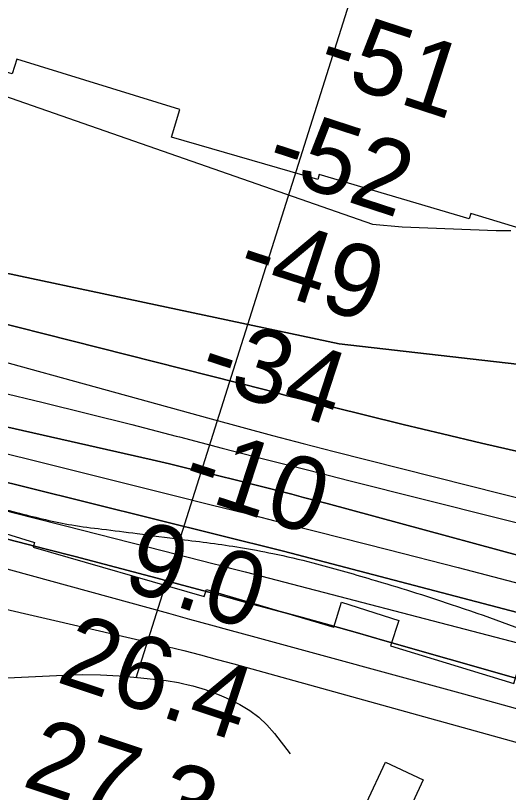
# Model space of a CAD drawing. Extents: x 3361039 to 3398939, y 576572 to 602007.
# Drawn here: x 3389803 to 3390253, y 585118 to 585828 of the extents above; entities that cross this region are included whole.
import ezdxf

# ---------------------------------------------------------------- set-up
doc = ezdxf.new("R2010")
doc.units = 0
for name, color, linetype in [('V-BLDG-OTLN', 7, 'Continuous'), ('V-CHAN-NAID', 7, 'Continuous'), ('V-RIVR-EDGE', 7, 'Continuous'), ('V-RIVR-RANG', 7, 'Continuous'), ('V-RRAP-RVMT', 7, 'Continuous'), ('V-TOPO-DPTH', 7, 'Continuous'), ('V-TOPO-MAJR', 7, 'Continuous'), ('V-TOPO-MINR', 7, 'Continuous'), ('V-TOPO-WATR', 7, 'Continuous'), ('V-UTIL-LINE', 7, 'Continuous')]:
    doc.layers.add(name, color=color, linetype=linetype)

msp = doc.modelspace()

# ---------------------------------------------------------------- linework, layer by layer
at = {"layer": 'V-BLDG-OTLN'}
msp.add_lwpolyline([(3390157.86, 585092.69), (3390123.44, 585108.75), (3390140.7, 585145.73), (3390175.12, 585129.67)], close=True, dxfattribs=at)
at = {"layer": 'V-RIVR-EDGE'}
msp.add_spline([(3387368.61, 585771.04), (3387388.99, 585767.6), (3387407.26, 585766.09), (3387418.22, 585761.68), (3387425.51, 585756.54), (3387441.59, 585752.85), (3387452.55, 585751.36), (3387462.06, 585753.9), (3387477.43, 585758.24), (3387482.91, 585759.33), (3387491.69, 585759.31), (3387502.28, 585758.18), (3387510.32, 585756.34), (3387521.64, 585753.02), (3387530.05, 585752.27), (3387538.46, 585752.24), (3387549.79, 585752.22), (3387558.94, 585755.48), (3387571.37, 585756.92), (3387583.43, 585757.25), (3387598.42, 585756.12), (3387629.84, 585749.46), (3387659.8, 585743.54), (3387703.28, 585736.85), (3387727.4, 585734.23), (3387739.1, 585733.47), (3387750.8, 585734.17), (3387753.72, 585731.61), (3387763.2, 585723.91), (3387774.52, 585720.59), (3387790.61, 585719.82), (3387800.12, 585721.62), (3387814, 585720.13), (3387824.6, 585720.1), (3387847.25, 585714.2), (3387884.16, 585709.35), (3387930.2, 585702.66), (3387980.65, 585701.07), (3388035.1, 585696.55), (3388076.04, 585694.62), (3388096.87, 585693.84), (3388120.26, 585690.49), (3388145.1, 585685.31), (3388171.78, 585682.32), (3388198.82, 585676.77), (3388222.56, 585669.4), (3388245.57, 585660.57), (3388260.91, 585655.42), (3388279.55, 585655.37), (3388291.26, 585658.26), (3388298.95, 585663.73), (3388299.32, 585666.29), (3388298.96, 585670.67), (3388290.56, 585674.35), (3388291.67, 585677.27), (3388293.86, 585678.36), (3388303, 585677.61), (3388318.72, 585676.47), (3388334.06, 585672.78), (3388354.14, 585663.59), (3388357.06, 585659.93), (3388363.27, 585658.09), (3388368.39, 585658.07), (3388370.95, 585660.99), (3388375.34, 585662.08), (3388379, 585661.34), (3388383.01, 585659.13), (3388383.73, 585654.38), (3388384.08, 585649.26), (3388389.93, 585647.42), (3388406, 585642.26), (3388468.86, 585637.72), (3388491.52, 585635.84), (3388534.64, 585628.42), (3388578.12, 585619.17), (3388610.64, 585613.61), (3388635.85, 585612.08), (3388727.94, 585599.43), (3388768.5, 585591.65), (3388822.57, 585580.92), (3388864.95, 585570.58), (3388906.6, 585562.8), (3388924.14, 585559.46), (3388938.77, 585561.99), (3388961.44, 585563.39), (3388974.22, 585560.07), (3389007.47, 585553.41), (3389018.81, 585554.48), (3389027.22, 585555.92), (3389037.09, 585555.89), (3389051.7, 585553.67), (3389061.21, 585553.28), (3389081.31, 585552.13), (3389098.12, 585550.99), (3389120.42, 585548.74), (3389143.44, 585546.49), (3389160.24, 585542.06), (3389200.8, 585534.65), (3389222.35, 585525.1), (3389247.19, 585519.19), (3389280.43, 585509.6), (3389307.45, 585497.83), (3389334.48, 585487.17), (3389349.45, 585483.11), (3389361.52, 585483.08), (3389382.71, 585479.01), (3389396.96, 585476.78), (3389416.68, 585468.69), (3389441.88, 585458.39), (3389464.89, 585451.39), (3389479.5, 585449.16), (3389506.18, 585446.17), (3389533.23, 585447.2), (3389558.45, 585444.21), (3389577.81, 585437.95), (3389603.38, 585431.3), (3389618.72, 585425.05), (3389639.16, 585415.13), (3389657.8, 585410.33), (3389693.24, 585404.76), (3389768.86, 585383.01), (3389806.48, 585373.05), (3389854.34, 585362.33), (3389881.75, 585358.6), (3389913.91, 585354.5), (3389953.74, 585349.29), (3390008.19, 585341.84), (3390037.78, 585336.28), (3390074.32, 585327.79), (3390128.02, 585312.67), (3390164.54, 585301.61), (3390200.7, 585289.82), (3390292.74, 585255.6), (3390327.06, 585241.26), (3390360.67, 585231.67), (3390404.51, 585220.96), (3390454.94, 585214.26), (3390483.08, 585210.53), (3390491.85, 585209.41), (3390494.4, 585207.21), (3390501.33, 585200.98), (3390507.91, 585200.6), (3390527.27, 585196.17), (3390545.91, 585195.02), (3390557.61, 585194.26), (3390574.41, 585189.83), (3390605.46, 585179.52), (3390698.6, 585148.22), (3390763.25, 585126.86), (3390811.09, 585111.02), (3390852.37, 585097.76), (3390900.95, 585081.56), (3390948.06, 585063.53), (3390993.71, 585048.43), (3391036.81, 585031.87), (3391070.77, 585020.09), (3391140.54, 584997.62), (3391201.53, 584974.07), (3391247.54, 584957.51), (3391310.73, 584933.59), (3391362.22, 584914.82), (3391400.57, 584900.1), (3391441.84, 584885.75), (3391505.38, 584861.1), (3391563.46, 584841.95), (3391658.78, 584807.35), (3391712.83, 584786.01), (3391758.84, 584767.26), (3391796.08, 584749.62), (3391880.45, 584718.34), (3391926.83, 584701.41), (3391969.2, 584685.22), (3392003.88, 584666.85), (3392040.03, 584650.32), (3392077.64, 584635.97), (3392135.71, 584613.16), (3392164.91, 584598.1), (3392195.95, 584583.77), (3392224.82, 584578.21), (3392263.54, 584567.88), (3392290.57, 584559.77), (3392322.7, 584546.53), (3392396.46, 584512.72), (3392439.92, 584496.16), (3392471.69, 584484.75), (3392502.01, 584473.34), (3392510.77, 584467.47), (3392535.24, 584458.27), (3392606.09, 584432.88), (3392632.38, 584421.48), (3392666.71, 584406.77), (3392715.64, 584386.91), (3392777.36, 584364.83), (3392827.04, 584348.25), (3392863.56, 584335.37), (3392897.89, 584321.76), (3392928.56, 584307.79), (3392965.45, 584294.91), (3393010.01, 584279.08), (3393054.56, 584263.25), (3393092.54, 584248.53), (3393195.16, 584206.61), (3393234.23, 584187.87), (3393264.53, 584173.54), (3393294.11, 584162.13), (3393336.85, 584147.4), (3393374.47, 584136.34), (3393402.23, 584127.5), (3393414.27, 584119.8), (3393435.45, 584109.14), (3393459.18, 584098.12), (3393478.9, 584087.47), (3393513.6, 584076.42), (3393541.72, 584067.21), (3393588.1, 584047.35), (3393643.25, 584028.94), (3393668.44, 584018.28), (3393699.85, 584005.04), (3393737.1, 583991.79), (3393781.66, 583975.96), (3393884.66, 583943.17), (3393927.03, 583928.81), (3393981.08, 583908.2), (3394043.9, 583885.38), (3394095.77, 583868.08), (3394154.93, 583847.09), (3394200.22, 583830.53), (3394246.97, 583816.16), (3394293, 583801.42), (3394349.61, 583781.18), (3394409.13, 583754.71), (3394451.84, 583730.48), (3394470.45, 583720.2), (3394481.77, 583715.42), (3394494.2, 583713.56), (3394502.59, 583708.06), (3394507.32, 583700.37), (3394511.34, 583697.8), (3394522.66, 583692.29), (3394557.34, 583675.75), (3394600.44, 583659.93), (3394658.14, 583638.95), (3394704.53, 583623.48), (3394760.42, 583607.62), (3394823.98, 583588.82), (3394867.8, 583570.8), (3394925.86, 583546.9), (3394972.24, 583528.87), (3394995.62, 583520.04), (3395064.67, 583504.15), (3395088.42, 583499.34), (3395120.2, 583491.59), (3395149.05, 583480.55), (3395173.17, 583476.83), (3395201.3, 583471.28), (3395236.37, 583459.86), (3395256.82, 583451.77), (3395280.93, 583445.5), (3395300.3, 583445.08), (3395316.74, 583440.65), (3395324.4, 583433.32), (3395335.35, 583425.99), (3395353.6, 583417.9), (3395398.9, 583403.9), (3395426.3, 583397.25), (3395442, 583391), (3395455.87, 583383.28), (3395475.96, 583377.75), (3395495.68, 583369.3), (3395511.03, 583368.16), (3395530.4, 583365.92), (3395550.49, 583361.85), (3395654.61, 583334.91), (3395704.66, 583322.35), (3395743.73, 583306.9), (3395765.27, 583295.52), (3395788.28, 583286.32), (3395816.41, 583278.94), (3395861.72, 583270.79), (3395916.16, 583261.52), (3395960.74, 583252.63), (3396008.6, 583242.64), (3396060.84, 583230.45), (3396093.36, 583222.33), (3396135.36, 583208.7), (3396170.06, 583199.84), (3396204.41, 583191.35), (3396254.82, 583177.33), (3396301.21, 583165.89), (3396364.42, 583152.94), (3396399.13, 583144.44), (3396426.89, 583138.53), (3396463.07, 583132.95), (3396489.75, 583132.89), (3396523.38, 583130.24), (3396607.78, 583113.95), (3396670.26, 583102.1), (3396708.26, 583095.43), (3396742.97, 583089.49), (3396775.14, 583083.89)], degree=3, dxfattribs=at)
at = {"layer": 'V-RRAP-RVMT'}
for points in [[(3390685.67, 585128.98), (3390783.67, 585465.57), (3390648.79, 585504.77), (3390652.15, 585515.73), (3390497.27, 585563.32), (3390495.91, 585558.78), (3390372.37, 585595.5), (3390373.65, 585599.69), (3390218.61, 585646.71), (3390217.09, 585641.79), (3390080.09, 585682.41), (3390078.74, 585677.73), (3389945.12, 585716.32), (3389952.93, 585741.58), (3389803.96, 585787.62), (3389799.66, 585774.23), (3389655.46, 585815.76), (3389654.54, 585812.59)], [(3389621.67, 585422.23), (3389686.86, 585403.36), (3389682.33, 585388.94), (3389820.19, 585346.35), (3389818.96, 585342.03), (3389975.24, 585296.89), (3389977.11, 585303.44), (3390093.64, 585268.89), (3390100.38, 585291.75), (3390152.85, 585275.19), (3390145.31, 585251.84), (3390257.77, 585217.55), (3390265.06, 585241.64), (3390403.8, 585200.41), (3390405.3, 585205.45), (3390543.76, 585162.9), (3390545.79, 585169.6), (3390685.67, 585128.98)]]:
    msp.add_lwpolyline(points, dxfattribs=at)
at = {"layer": 'V-TOPO-DPTH'}
for points in [[(3390700.76, 585459.2), (3390696.68, 585459.27), (3390098.42, 585527.64), (3389590.68, 585635.53), (3389096.91, 585679.59), (3389066.5, 585682.45), (3389036.09, 585685.39), (3388988.52, 585690.09), (3388981.91, 585690.78), (3388975.31, 585691.53), (3388968.72, 585692.37), (3388962.13, 585693.26), (3388917.5, 585699.6), (3388888.6, 585703.72), (3388859.7, 585707.84), (3388830.81, 585711.98), (3388801.92, 585716.13), (3388286.49, 585790.27)], [(3388286.49, 585790.27), (3388801.92, 585716.13), (3388830.81, 585711.98), (3388859.7, 585707.84), (3388888.6, 585703.72), (3388917.5, 585699.6), (3388962.13, 585693.26), (3388968.72, 585692.37), (3388975.31, 585691.53), (3388981.91, 585690.78), (3388988.52, 585690.09), (3389036.09, 585685.39), (3389066.5, 585682.45), (3389096.91, 585679.59), (3389590.68, 585635.53), (3390098.42, 585527.64), (3390696.68, 585459.27), (3390700.76, 585459.2)], [(3389027.37, 585637.37), (3389431.82, 585588.53), (3389455.77, 585585.56), (3389479.7, 585582.51), (3389503.62, 585579.32), (3389527.52, 585576.03), (3389539.33, 585574.37), (3389557.26, 585571.56), (3389575.12, 585568.38), (3389592.87, 585564.62), (3389610.55, 585560.49), (3389628.15, 585556.02), (3389645.74, 585551.46), (3389663.29, 585546.78), (3389680.81, 585542.01), (3389981.42, 585459.13), (3390009.45, 585451.5), (3390037.52, 585443.99), (3390065.63, 585436.66), (3390093.78, 585429.46), (3390401.22, 585351.83)], [(3389027.37, 585637.37), (3389431.82, 585588.53), (3389455.77, 585585.56), (3389479.7, 585582.51), (3389503.62, 585579.32), (3389527.52, 585576.03), (3389539.33, 585574.37), (3389557.26, 585571.56), (3389575.12, 585568.38), (3389592.87, 585564.62), (3389610.55, 585560.49), (3389628.15, 585556.02), (3389645.74, 585551.46), (3389663.29, 585546.78), (3389680.81, 585542.01), (3389981.42, 585459.13), (3390009.45, 585451.5), (3390037.52, 585443.99), (3390065.63, 585436.66), (3390093.78, 585429.46), (3390401.22, 585351.83)], [(3390707.62, 585326.61), (3390672.42, 585334.93), (3390637.19, 585343.15), (3390601.95, 585351.29), (3390264.28, 585428.83), (3390228.42, 585437.15), (3390192.59, 585445.59), (3390156.8, 585454.2), (3390121.04, 585462.93), (3390068.3, 585475.93), (3390058.94, 585478.28), (3390049.59, 585480.7), (3390040.27, 585483.2), (3390030.97, 585485.77), (3389602.71, 585594.09), (3389592.39, 585596.36), (3389582.03, 585598.41), (3389571.61, 585600.11), (3389561.14, 585601.58), (3389457.28, 585614.43), (3389394.83, 585622), (3389332.36, 585629.35)], [(3389332.36, 585629.35), (3389394.83, 585622), (3389457.28, 585614.43), (3389561.14, 585601.58), (3389571.61, 585600.11), (3389582.03, 585598.41), (3389592.39, 585596.36), (3389602.71, 585594.09), (3390030.97, 585485.77), (3390040.27, 585483.2), (3390049.59, 585480.7), (3390058.94, 585478.28), (3390068.3, 585475.93), (3390121.04, 585462.93), (3390156.8, 585454.2), (3390192.59, 585445.59), (3390228.42, 585437.15), (3390264.28, 585428.83), (3390601.95, 585351.29), (3390637.19, 585343.15), (3390672.42, 585334.93), (3390707.62, 585326.61)], [(3390745.08, 585150.09), (3390651.51, 585182.68), (3390626.84, 585192.1), (3390614.08, 585196.39), (3390591.96, 585202.41), (3390336.68, 585262.64), (3390047.39, 585338.28), (3389812.55, 585396.75), (3389593.02, 585450.94), (3389572.59, 585456.1), (3389556.43, 585460.39), (3389535.16, 585466.4), (3389062.85, 585558.67), (3388971.78, 585572.52), (3388953.91, 585574.27), (3388926.67, 585578.59), (3388768.38, 585604.53)], [(3388768.38, 585604.53), (3388926.67, 585578.59), (3388953.91, 585574.27), (3388971.78, 585572.52), (3389062.85, 585558.67), (3389535.16, 585466.4), (3389556.43, 585460.39), (3389572.59, 585456.1), (3389593.02, 585450.94), (3389812.55, 585396.75), (3390047.39, 585338.28), (3390336.68, 585262.64), (3390591.96, 585202.41), (3390614.08, 585196.39), (3390626.84, 585192.1), (3390651.51, 585182.68), (3390745.08, 585150.09)], [(3390576.09, 585249.3), (3390087.4, 585381.81), (3390076.63, 585384.7), (3390065.84, 585387.56), (3390055.05, 585390.36), (3390044.25, 585393.13), (3390033.44, 585395.87), (3390022.62, 585398.61), (3390011.81, 585401.34), (3390001, 585404.06), (3389990.99, 585406.59), (3389975.16, 585410.51), (3389959.31, 585414.36), (3389943.43, 585418.1), (3389927.53, 585421.75), (3389584.29, 585499.36), (3389572.35, 585501.97), (3389560.39, 585504.47), (3389548.39, 585506.8), (3389536.37, 585509.02), (3389018.93, 585600.81)], [(3389018.93, 585600.81), (3389536.37, 585509.02), (3389548.39, 585506.8), (3389560.39, 585504.47), (3389572.35, 585501.97), (3389584.29, 585499.36), (3389927.53, 585421.75), (3389943.43, 585418.1), (3389959.31, 585414.36), (3389975.16, 585410.51), (3389990.99, 585406.59), (3390001, 585404.06), (3390011.81, 585401.34), (3390022.62, 585398.61), (3390033.44, 585395.87), (3390044.25, 585393.13), (3390055.05, 585390.36), (3390065.84, 585387.56), (3390076.63, 585384.7), (3390087.4, 585381.81), (3390576.09, 585249.3)], [(3390553.25, 585138.62), (3390140.17, 585256.63), (3390115.13, 585263.73), (3390090.07, 585270.77), (3390064.98, 585277.71), (3390039.87, 585284.58), (3390014.75, 585291.39), (3389989.62, 585298.18), (3389964.49, 585304.95), (3389939.35, 585311.71), (3389936.74, 585312.41), (3389910.28, 585319.46), (3389883.81, 585326.47), (3389857.32, 585333.4), (3389830.82, 585340.29), (3389571.68, 585407.25), (3389555.78, 585411.31), (3389539.85, 585415.29), (3389523.9, 585419.18), (3389507.94, 585423), (3389318.25, 585467.7)]]:
    msp.add_lwpolyline(points, dxfattribs=at)
at = {"layer": 'V-TOPO-MAJR'}
for points in [[(3389141.94, 585894.31), (3389612.25, 585812.11), (3389630.24, 585808.1), (3389648.05, 585803.37), (3389665.75, 585798.18), (3390128.66, 585637.09), (3390155.78, 585634.5), (3390241.62, 585631.1), (3390254.99, 585631.19)], [(3389776.18, 585221.8), (3389846.64, 585225.23), (3389863.57, 585225.65), (3389880.47, 585225.54), (3389897.35, 585224.61), (3389914.22, 585223.15), (3389940.44, 585220.24), (3389944.17, 585219.76), (3389947.89, 585219.19), (3389951.58, 585218.49), (3389955.26, 585217.71), (3389960.44, 585216.51), (3389964.73, 585215.35), (3389975.88, 585211.96), (3389982.44, 585209.76), (3389988.91, 585207.33), (3389995.24, 585204.55), (3390001.47, 585201.54), (3390007.78, 585198.27), (3390016.65, 585192.92), (3390024.95, 585186.87), (3390032.38, 585179.8), (3390039.24, 585172.03), (3390053.65, 585153.38)]]:
    msp.add_lwpolyline(points, dxfattribs=at)
at = {"layer": 'V-TOPO-MINR'}
for points in [[(3390700.76, 585459.2), (3390696.68, 585459.27), (3390098.42, 585527.64), (3389590.68, 585635.53), (3389096.91, 585679.59), (3389066.5, 585682.45), (3389036.09, 585685.39), (3388988.52, 585690.09), (3388981.91, 585690.78), (3388975.31, 585691.53), (3388968.72, 585692.37), (3388962.13, 585693.26), (3388917.5, 585699.6), (3388888.6, 585703.72), (3388859.7, 585707.84), (3388830.81, 585711.98), (3388801.92, 585716.13), (3388286.49, 585790.27)], [(3389027.37, 585637.37), (3389431.82, 585588.53), (3389455.77, 585585.56), (3389479.7, 585582.51), (3389503.62, 585579.32), (3389527.52, 585576.03), (3389539.33, 585574.37), (3389557.26, 585571.56), (3389575.12, 585568.38), (3389592.87, 585564.62), (3389610.55, 585560.49), (3389628.15, 585556.02), (3389645.74, 585551.46), (3389663.29, 585546.78), (3389680.81, 585542.01), (3389981.42, 585459.13), (3390009.45, 585451.5), (3390037.52, 585443.99), (3390065.63, 585436.66), (3390093.78, 585429.46), (3390401.22, 585351.83)], [(3389332.36, 585629.35), (3389394.83, 585622), (3389457.28, 585614.43), (3389561.14, 585601.58), (3389571.61, 585600.11), (3389582.03, 585598.41), (3389592.39, 585596.36), (3389602.71, 585594.09), (3390030.97, 585485.77), (3390040.27, 585483.2), (3390049.59, 585480.7), (3390058.94, 585478.28), (3390068.3, 585475.93), (3390121.04, 585462.93), (3390156.8, 585454.2), (3390192.59, 585445.59), (3390228.42, 585437.15), (3390264.28, 585428.83), (3390601.95, 585351.29), (3390637.19, 585343.15), (3390672.42, 585334.93), (3390707.62, 585326.61)], [(3389018.93, 585600.81), (3389536.37, 585509.02), (3389548.39, 585506.8), (3389560.39, 585504.47), (3389572.35, 585501.97), (3389584.29, 585499.36), (3389927.53, 585421.75), (3389943.43, 585418.1), (3389959.31, 585414.36), (3389975.16, 585410.51), (3389990.99, 585406.59), (3390001, 585404.06), (3390011.81, 585401.34), (3390022.62, 585398.61), (3390033.44, 585395.87), (3390044.25, 585393.13), (3390055.05, 585390.36), (3390065.84, 585387.56), (3390076.63, 585384.7), (3390087.4, 585381.81), (3390576.09, 585249.3)], [(3389327.82, 585575.29), (3389511.62, 585545.41), (3389539.6, 585540.55), (3389567.5, 585535.29), (3389595.28, 585529.41), (3389622.98, 585523.14), (3389787.46, 585483.98), (3389828.07, 585474.18), (3389868.64, 585464.19), (3389909.14, 585453.94), (3389949.59, 585443.51), (3389952.52, 585442.74), (3389991.49, 585432.62), (3390030.48, 585422.57), (3390069.5, 585412.62), (3390108.54, 585402.75), (3390646.36, 585267.58), (3390647.4, 585267.31), (3390649.23, 585266.85), (3390652.76, 585265.88), (3390656.01, 585264.91), (3391449.41, 585019.99)], [(3389354.76, 585521.58), (3389395.01, 585514.39), (3389435.24, 585507.09), (3389475.46, 585499.73), (3389551.85, 585485.66), (3389555.87, 585484.88), (3389557.88, 585484.46), (3389559.88, 585484.03), (3389592.26, 585476.87), (3389610.43, 585472.78), (3389628.58, 585468.59), (3389646.7, 585464.25), (3389664.79, 585459.82), (3389948.9, 585389.01), (3389981.51, 585380.86), (3390014.11, 585372.67), (3390046.69, 585364.43), (3390079.27, 585356.16), (3390142.65, 585340.02), (3390206.87, 585323.5), (3390271.03, 585306.78)], [(3389119.4, 585492.72), (3389525.69, 585394.54), (3389530.13, 585393.45), (3389534.57, 585392.34), (3389539, 585391.21), (3389543.43, 585390.06), (3389580.63, 585380.31), (3389603.65, 585374.23), (3389626.65, 585368.1), (3389649.63, 585361.89), (3389672.6, 585355.64), (3389942.43, 585281.66), (3389961.59, 585276.41), (3389980.74, 585271.17), (3389999.9, 585265.94), (3390019.05, 585260.71), (3390211.77, 585208.16), (3390275.53, 585190.64)], [(3389314.77, 585490.06), (3389372.52, 585477.85), (3389430.16, 585465.12), (3389489.83, 585451.53), (3389517.53, 585445.11), (3389545.2, 585438.55), (3389572.82, 585431.77), (3389600.41, 585424.85), (3389818.51, 585369.22), (3389848.41, 585361.59), (3389878.31, 585353.96), (3389908.21, 585346.31), (3389938.1, 585338.67), (3389983.14, 585327.14), (3389990.52, 585325.24), (3389997.89, 585323.34), (3390005.26, 585321.44), (3390012.63, 585319.52), (3390262.38, 585254.52)], [(3389106.58, 585471.89), (3389524.23, 585347.42), (3389542.47, 585343.37), (3389560.74, 585339.47), (3389941.2, 585251.51), (3389956.46, 585247.61), (3389971.7, 585243.64), (3389986.91, 585239.55), (3390002.11, 585235.4), (3390497.68, 585097.94), (3390512.16, 585093.9), (3390526.63, 585089.82), (3390541.09, 585085.69), (3390555.53, 585081.53), (3390569.93, 585077.23), (3390584.29, 585072.8), (3390598.58, 585068.14), (3390612.83, 585063.35), (3391305.14, 584824.7)], [(3389318.25, 585467.7), (3389507.94, 585423), (3389523.9, 585419.18), (3389539.85, 585415.29), (3389555.78, 585411.31), (3389571.68, 585407.25), (3389830.82, 585340.29), (3389857.32, 585333.4), (3389883.81, 585326.47), (3389910.28, 585319.46), (3389936.74, 585312.41), (3389939.35, 585311.71), (3389964.49, 585304.95), (3389989.62, 585298.18), (3390014.75, 585291.39), (3390039.87, 585284.58), (3390064.98, 585277.71), (3390090.07, 585270.77), (3390115.13, 585263.73), (3390140.17, 585256.63), (3390553.25, 585138.62)]]:
    msp.add_lwpolyline(points, dxfattribs=at)
at = {"layer": 'V-TOPO-WATR'}
msp.add_lwpolyline([(3390745.08, 585150.09), (3390651.51, 585182.68), (3390626.84, 585192.1), (3390614.08, 585196.39), (3390591.96, 585202.41), (3390336.68, 585262.64), (3390047.39, 585338.28), (3389812.55, 585396.75), (3389593.02, 585450.94), (3389572.59, 585456.1), (3389556.43, 585460.39), (3389535.16, 585466.4), (3389062.85, 585558.67), (3388971.78, 585572.52), (3388953.91, 585574.27), (3388926.67, 585578.59), (3388768.38, 585604.53)], dxfattribs=at)
at = {"layer": 'V-UTIL-LINE'}
msp.add_line((3389912.91, 585222.89), (3390850.7, 588187.96), dxfattribs=at)

# ---------------------------------------------------------------- texts
at = {"layer": 'V-CHAN-NAID'}
msp.add_text('BAYOU LAFOURCHE INTAKE (175.4) (2)', height=100, rotation=76.78368, dxfattribs=at).set_placement((3389221.84, 585787.16))
at = {"layer": 'V-RIVR-RANG'}
for s, rotation, p in [('-51', 341.94842, (3390075.67, 585772.64)), ('-52', 341.94842, (3390028.64, 585682.79)), ('-49', 341.94842, (3390002.19, 585586.24)), ('-34', 341.94842, (3389967.45, 585492.38)), ('-10', 341.94842, (3389951.78, 585392.31)), ('9.0', 341.66833, (3389898.72, 585304.88)), ('26.4', 341.66833, (3389838.7, 585219.42)), ('27.3', 341.66833, (3389807.48, 585124.42))]:
    msp.add_text(s, height=67, rotation=rotation, dxfattribs=at).set_placement(p)

doc.saveas('drawing.dxf')
